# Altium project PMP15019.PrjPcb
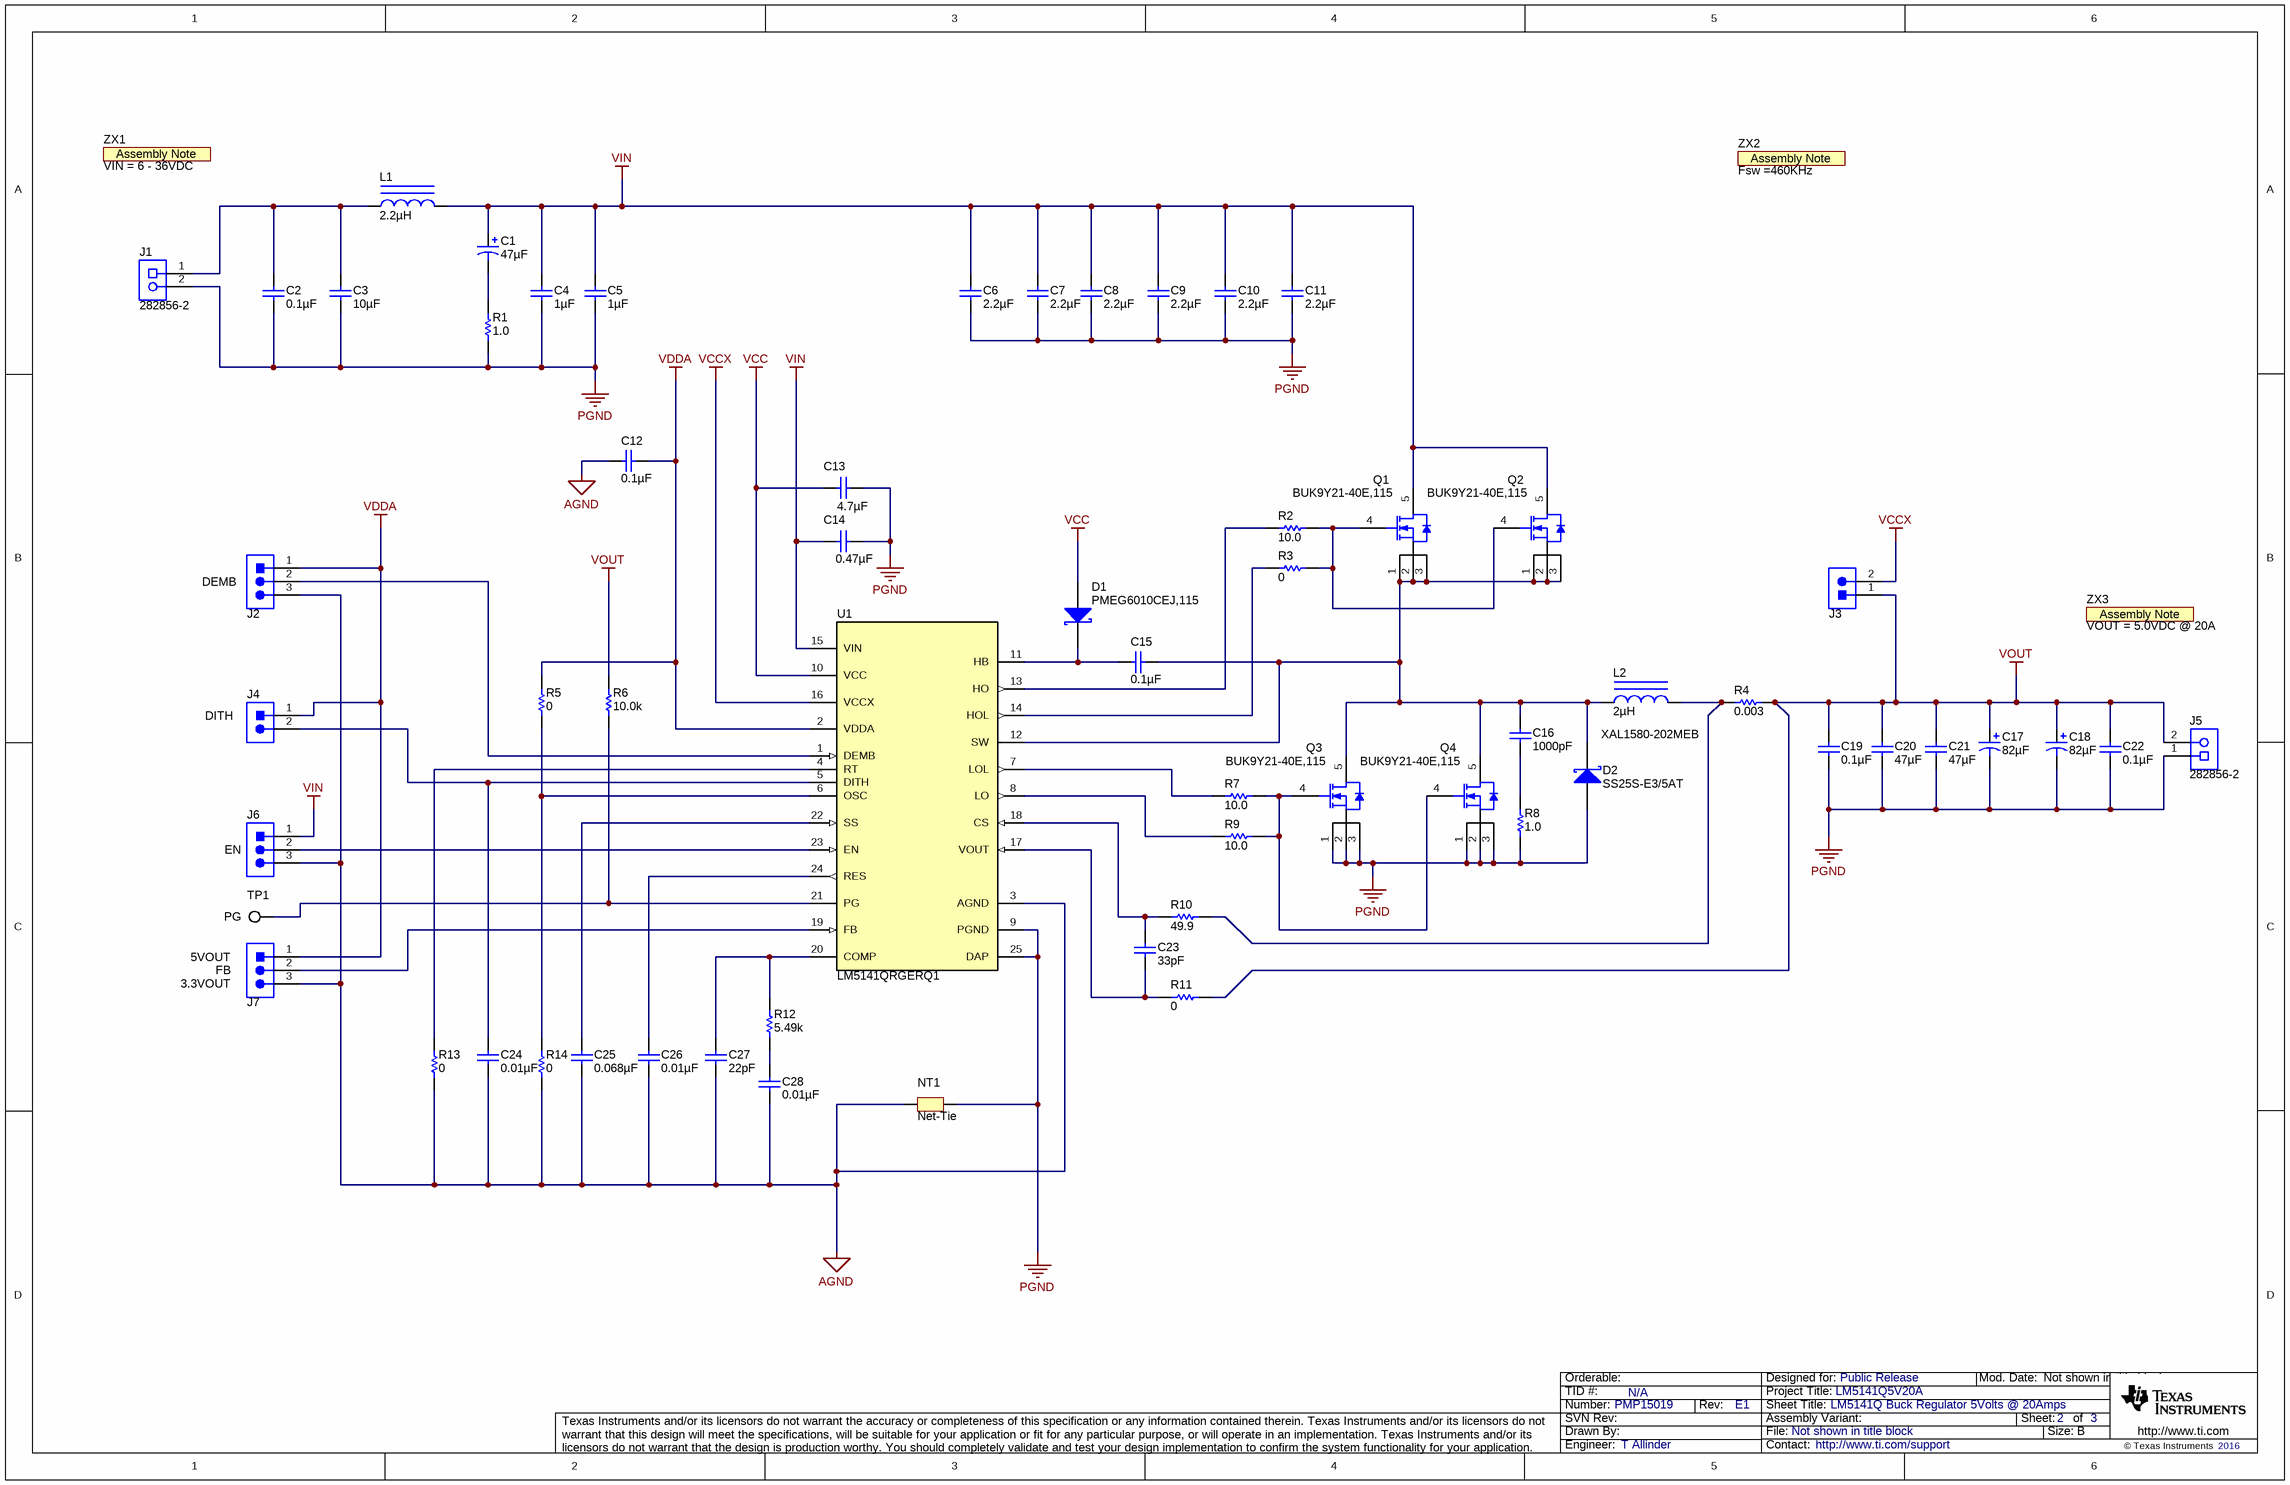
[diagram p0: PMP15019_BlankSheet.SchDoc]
TID: N/A; TechSupport: http://www.ti.com/support; SCH_Rev: E1; PRJ_Title: LM5141Q5V20A; PRJ_Number: PMP15019; PRJ_Engineer: T Allinder; PRJ_Customer: Public Release; PCB_Rev: E1; PCB_Layout: K Nielson; CopyrightYear: 2016
2 sheets, 87 parts. Net scope: global (net labels, ports and power ports of the same name join across sheets).
Board file: PMP15019_PCB.PcbDoc
Sheets:
  PMP15019_BlankSheet.SchDoc
  PMP15019_EVM_Hardware.SchDoc

## Sheet PMP15019_BlankSheet.SchDoc: LM5141Q Buck Regulator 5Volts @ 20Amps
size 431 x 279 mm; Date: Not shown in title block; ApprovedBy: Not shown in title block; CheckedBy: Not shown in title block; Author: Not shown in title block; CompanyName: Not shown in title block; Engineer: Not shown in title block; Organization: Not shown in title block; Address1: Not shown in title block; Address2: Not shown in title block; Address3: Not shown in title block; Address4: Not shown in title block; DocumentNumber: 1; Revision: Use project parameter SCH_Rev; SheetNumber: 2; SheetTotal: 3; PageSetup: Record=PageOptions¦CenterHorizontal=True¦CenterVertical=True¦PrintScale=1.00¦XCorrection=1.00¦YCorrection=1.00¦PrintKind=0¦BorderSize=5000000¦LeftOffset=0¦BottomOffset=0¦Orientation=2¦PaperLength=1000¦PaperWidth=1000¦Scale=100¦PaperSource=15¦PrintQuality=600¦MediaType=1¦DitherType=10¦PaperKind=Letter¦PrintScaleMode=1

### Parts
C1  ValueDisplayed: 47µF  [SM_RADIAL_G]  (hidden comment: EEE-FC1H470P)
C2  ValueDisplayed: 0.1µF  [0805_HV]  (hidden comment: C0805C104K1RACTU)
C3  ValueDisplayed: 10µF  [1210_280]  (hidden comment: C3225X7R1H106M250AC)
C4  ValueDisplayed: 1µF  [1206L]  (hidden comment: C3216X7R2A105M160AA)
C5  ValueDisplayed: 1µF  [1206L]  (hidden comment: C3216X7R2A105M160AA)
C6  ValueDisplayed: 2.2µF  [1206_190]  (hidden comment: CL31B225KCHSNNE)
C7  ValueDisplayed: 2.2µF  [1206_190]  (hidden comment: CL31B225KCHSNNE)
C8  ValueDisplayed: 2.2µF  [1206_190]  (hidden comment: CL31B225KCHSNNE)
C9  ValueDisplayed: 2.2µF  [1206_190]  (hidden comment: CL31B225KCHSNNE)
C10  ValueDisplayed: 2.2µF  [1206_190]  (hidden comment: CL31B225KCHSNNE)
C11  ValueDisplayed: 2.2µF  [1206_190]  (hidden comment: CL31B225KCHSNNE)
C12  ValueDisplayed: 0.1µF  [0603L]  (hidden comment: C0603C104K5RACTU)
C13  ValueDisplayed: 4.7µF  [0603L]  (hidden comment: GRM188R61C475KAAJ)
C14  ValueDisplayed: 0.47µF  [0805L]  (hidden comment: GRM21BR72A474KA73L)
C15  ValueDisplayed: 0.1µF  [0603L]  (hidden comment: C0603C104K5RACTU)
C16  ValueDisplayed: 1000pF  [0603L]  (hidden comment: GRM1885C2A102JA01D)
C17  ValueDisplayed: 82µF  [WCAP-PSLP_630x580]  (hidden comment: 875105344009)
C18  ValueDisplayed: 82µF  [WCAP-PSLP_630x580]  (hidden comment: 875105344009)
C19  ValueDisplayed: 0.1µF  [0603L]  (hidden comment: C0603C104K5RACTU)
C20  ValueDisplayed: 47µF  [1206]  (hidden comment: C3216X5R1C476M160AB)
C21  ValueDisplayed: 47µF  [1206]  (hidden comment: C3216X5R1C476M160AB)
C22  ValueDisplayed: 0.1µF  [0603L]  (hidden comment: C0603C104K5RACTU)
C23  ValueDisplayed: 33pF  [0603L]  (hidden comment: 06035A330JAT2A)
C24  ValueDisplayed: 0.01µF  [0603L]  (hidden comment: CGA3E2X7R2A103K080AA)
C25  ValueDisplayed: 0.068µF  [0603L]  (hidden comment: GRM188R71E683KA01D)
C26  ValueDisplayed: 0.01µF  [0603L]  (hidden comment: CGA3E2X7R2A103K080AA)
C27  ValueDisplayed: 22pF  [0603L]  (hidden comment: CGA3E2C0G1H220J080AA)
C28  ValueDisplayed: 0.01µF  [0603L]  (hidden comment: CGA3E2X7R2A103K080AA)
D1  PMEG6010CEJ,115  [SOD-323F]
D2  SS25S-E3/5AT  [SMA]
J1  282856-2  [TE_282856-2]
J2  TSW-103-07-G-S  [TSW-103-07-G-S]  (value not drawn)
J3  TSW-102-07-G-S  [TSW-102-07-G-S]  (value not drawn)
J4  TSW-102-07-G-S  [TSW-102-07-G-S]  (value not drawn)
J5  282856-2  [TE_282856-2]
J6  TSW-103-07-G-S  [TSW-103-07-G-S]  (value not drawn)
J7  TSW-103-07-G-S  [TSW-103-07-G-S]  (value not drawn)
L1  ValueDisplayed: 2.2µH  [WE-HCC_1090]  (hidden comment: 7443330220)
L2  XAL1580-202MEB  ValueDisplayed: 2µH  [XAL1580]
NT1  Net-Tie  [Net-Tie_10mil]  (net tie, no BOM)
Q1  BUK9Y21-40E,115  [LFPAK56]
Q2  BUK9Y21-40E,115  [LFPAK56]
Q3  BUK9Y21-40E,115  [LFPAK56]
Q4  BUK9Y21-40E,115  [LFPAK56]
R1  ValueDisplayed: 1.0  [1206]  (hidden comment: CRCW12061R00JNEA)
R2  ValueDisplayed: 10.0  [0603S]  (hidden comment: CRCW060310R0FKEAHP)
R3  ValueDisplayed: 0  [0603S]  (hidden comment: CRCW06030000Z0EA)
R4  0.003  [2512_WIDE]
R5  ValueDisplayed: 0  [0603L]  (hidden comment: CRCW06030000Z0EA)
R6  ValueDisplayed: 10.0k  [0603L]  (hidden comment: CRCW060310K0FKEA)
R7  ValueDisplayed: 10.0  [0603S]  (hidden comment: CRCW060310R0FKEAHP)
R8  ValueDisplayed: 1.0  [1206]  (hidden comment: CRM1206-JW-1R0ELF)
R9  ValueDisplayed: 10.0  [0603S]  (hidden comment: CRCW060310R0FKEAHP)
R10  ValueDisplayed: 49.9  [0603L]  (hidden comment: CRCW060349R9FKEA)
R11  ValueDisplayed: 0  [0603L]  (hidden comment: CRCW06030000Z0EA)
R12  ValueDisplayed: 5.49k  [0603L]  (hidden comment: CRCW06035K49FKEA)
R13  ValueDisplayed: 0  [0603L]  (hidden comment: CRCW06030000Z0EA)
R14  ValueDisplayed: 0  [0603L]  (hidden comment: CRCW06030000Z0EA)
TP1  5002  [Keystone5002]  (value not drawn)
U1  LM5141QRGERQ1  [RGE0024H]
ZX1  VIN = 6 - 36VDC  [AssemblyNote]  (no BOM)
ZX2  Fsw =460KHz  [AssemblyNote]  (no BOM)
ZX3  VOUT = 5.0VDC @ 20A  [AssemblyNote]  (no BOM)

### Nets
AGND: C12.1 C24.2 C25.2 C26.2 C27.2 C28.2 J2.3 J6.3 J7.3 NT1.1 R13.1 R14.2 U1.3(AGND)
PGND: C2.2 C3.2 C4.2 C5.2 C6.2 C7.2 C8.2 C9.2 C10.2 C11.2 C13.1 C14.1 C17.2(-) C18.2(-) C19.2 C20.2 C21.2 C22.2 D2.2(A) J1.2 J5.1 NT1.2 Q3.1(S) Q3.2(S) Q3.3(S) Q4.1(S) Q4.2(S) Q4.3(S) R1.1 R8.1 U1.9(PGND) U1.25(DAP)
VCC: C13.2 D1.2(A) U1.10(VCC)
VCCX: J3.2 U1.16(VCCX)
VDDA: C12.2 J2.1 J4.1 J7.1 R5.1 U1.2(VDDA)
VIN: C1.1(+) C4.1 C5.1 C6.1 C7.1 C8.1 C9.1 C10.1 C11.1 C14.2 J6.1 L1.2 Q1.5(D) Q2.5(D) U1.15(VIN)
VOUT: C17.1(+) C18.1(+) C19.1 C20.1 C21.1 C22.1 J3.1 J5.2 R4.2 R6.1 R11.2
NetC1_2: C1.2(-) R1.2
NetC2_1: C2.1 C3.1 J1.1 L1.1
NetC15_1: C15.1 D1.1(K) U1.11(HB)
NetC15_2: C15.2 C16.1 D2.1(K) L2.1 Q1.1(S) Q1.2(S) Q1.3(S) Q2.1(S) Q2.2(S) Q2.3(S) Q3.5(D) Q4.5(D) U1.12(SW)
NetC16_2: C16.2 R8.2
NetC23_1: C23.1 R11.1 U1.17(VOUT)
NetC23_2: C23.2 R10.1 U1.18(CS)
NetC24_1: C24.1 J4.2 U1.5(DITH)
NetC25_1: C25.1 U1.22(SS)
NetC26_1: C26.1 U1.24(RES)
NetC27_1: C27.1 R12.2 U1.20(COMP)
NetC28_1: C28.1 R12.1
NetJ2_2: J2.2 U1.1(DEMB)
NetJ6_2: J6.2 U1.23(EN)
NetJ7_2: J7.2 U1.19(FB)
NetL2_2: L2.2 R4.1 R10.2
NetQ1_4: Q1.4(G) Q2.4(G) R2.2 R3.1
NetQ3_4: Q3.4(G) Q4.4(G) R7.2 R9.1
NetR2_1: R2.1 U1.13(HO)
NetR3_2: R3.2 U1.14(HOL)
NetR5_2: R5.2 R14.1 U1.6(OSC)
NetR6_2: R6.2 TP1.1 U1.21(PG)
NetR7_1: R7.1 U1.7(LOL)
NetR9_2: R9.2 U1.8(LO)
NetR13_2: R13.2 U1.4(RT)

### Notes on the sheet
- (near J2) DEMB
- (near J4) DITH
- (near J6) EN
- 5VOUT
- FB
- (near TP1) PG
- 3.3VOUT

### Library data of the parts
C1 = EEE-FC1H470P: CAP, AL, 47 µF, 50 V, +/- 20%, 0.3 ohm, SMD; Manufacturer: Panasonic; Polarized: Y; CompType: Capacitor; Value: 47uF; U/M: EA; Cap_F: 0.000047; Tolerance_%: 20; Value1: 0.3 ohm; VDC_V: 50; Value2: 50V; ESR_ohm: 0.3; IRMS_A: 0.5; TaMin_C: -40; TaMax_C: 105; Cap_Case: G
C2 = C0805C104K1RACTU: CAP, CERM, 0.1 µF, 100 V, +/- 10%, X7R, 0805; Manufacturer: Kemet; Polarized: N; CompType: Capacitor; Value: 0.1uF; U/M: EA; Cap_F: 0.0000001; Tolerance_%: 10; ESR_ohm: 0.064; Value1: 0.064 ohm; VDC_V: 100; Value2: 100V; IRMS_A: 1.64; TaMin_C: -55; TaMax_C: 125; Cap_Case: 0805
C3 = C3225X7R1H106M250AC: CAP, CERM, 10 µF, 50 V, +/- 20%, X7R, 1210; Manufacturer: TDK; Polarized: N; CompType: Capacitor; Value: 10uF; U/M: EA; Cap_F: 0.00001; Tolerance_%: 20; Value1: Unknown; VDC_V: 50; Value2: 50V; TaMin_C: -55; TaMax_C: 125; Cap_Case: 1210
C4 C5 = C3216X7R2A105M160AA: CAP, CERM, 1 µF, 100 V, +/- 20%, X7R, 1206; Manufacturer: TDK; Polarized: N; CompType: Capacitor; Value: 1uF; U/M: EA; Cap_F: 0.000001; Tolerance_%: 20; Value1: Unknown; VDC_V: 100; Value2: 100V; TaMin_C: -55; TaMax_C: 125; Cap_Case: 1206
C6-C11 = CL31B225KCHSNNE: CAP, CERM, 2.2 µF, 100 V, +/- 10%, X7R, 1206_190; Manufacturer: Samsung Electro-Mechanics; Polarized: N; CompType: Capacitor; Value: 2.2uF; U/M: EA; Cap_F: 0.0000022; Tolerance_%: 10; Value1: Unknown; VDC_V: 100; Value2: 100V; TaMin_C: -55; TaMax_C: 125; Cap_Case: 1206
C12 C15 C19 C22 = C0603C104K5RACTU: CAP, CERM, 0.1 µF, 50 V, +/- 10%, X7R, 0603; Manufacturer: Kemet; Polarized: N; CompType: Capacitor; Value: 0.1uF; U/M: EA; Cap_F: 0.0000001; Tolerance_%: 10; Value1: Unknown; VDC_V: 50; Value2: 50V; TaMin_C: -55; TaMax_C: 125; Cap_Case: 0603
C13 = GRM188R61C475KAAJ: CAP, CERM, 4.7 µF, 16 V, +/- 10%, X5R, 0603; Manufacturer: MuRata; Polarized: N; CompType: Capacitor; Value: 4.7uF; U/M: EA; Cap_F: 0.0000047; Tolerance_%: 10; Value1: Unknown; VDC_V: 16; Value2: 16V; TaMin_C: -55; TaMax_C: 85; Cap_Case: 0603
C14 = GRM21BR72A474KA73L: CAP, CERM, 0.47 µF, 100 V, +/- 10%, X7R, 0805; Manufacturer: MuRata; Polarized: N; CompType: Capacitor; Value: 0.47uF; U/M: EA; Cap_F: 0.00000047; Tolerance_%: 10; Value1: Unknown; VDC_V: 100; Value2: 100V; TaMin_C: -55; TaMax_C: 125; Cap_Case: 0805
C16 = GRM1885C2A102JA01D: CAP, CERM, 1000 pF, 100 V, +/- 5%, C0G/NP0, 0603; Manufacturer: MuRata; Polarized: N; CompType: Capacitor; Value: 1000pF; U/M: EA; Cap_F: 0.000000001; Tolerance_%: 5; Value1: Unknown; VDC_V: 100; Value2: 100V; TaMin_C: -55; TaMax_C: 125; Cap_Case: 0603
C17 C18 = 875105344009: CAP, Aluminum Polymer, 82 µF, 16 V, +/- 20%, 0.03 ohm, D6.3xL5.8mm SMD; Manufacturer: Wurth Elektronik; Polarized: Y; CompType: Capacitor; Value: 82uF; U/M: EA; Cap_F: 0.000082; Tolerance_%: 20; VDC_V: 16; Value2: 16V; ESR_ohm: 0.03; IRMS_A: 2.2; TaMin_C: -55; TaMax_C: 105; Cap_Case: 6.3x5.8mm
C20 C21 = C3216X5R1C476M160AB: CAP, CERM, 47 µF, 16 V, +/- 15%, X5R, 1206; Manufacturer: TDK; Polarized: N; CompType: Capacitor; Value: 47uF; U/M: EA; Cap_F: 0.000047; Tolerance_%: 15; Value1: Unknown; VDC_V: 16; Value2: 16V; TaMin_C: -55; TaMax_C: 85
C23 = 06035A330JAT2A: CAP, CERM, 33 pF, 50 V, +/- 5%, C0G/NP0, 0603; Manufacturer: AVX; Polarized: N; CompType: Capacitor; Value: 33pF; U/M: EA; Cap_F: 0.000000000033; Tolerance_%: 5; ESR_ohm: 0.209; Value1: 0.209 ohm; VDC_V: 50; Value2: 50V; TaMin_C: -55; TaMax_C: 125; Cap_Case: 0603
C24 C26 C28 = CGA3E2X7R2A103K080AA: CAP, CERM, 0.01 µF, 100 V, +/- 10%, X7R, AEC-Q200 Grade 1, 0603; Manufacturer: TDK; Polarized: N; CompType: Capacitor; Value: 0.01uF; U/M: EA; Cap_F: 0.00000001; Tolerance_%: 10; ESR_ohm: 0.235428; Value1: 0.235428 ohm; VDC_V: 100; Value2: 100V; IRMS_A: 0.396995; TaMin_C: -55; TaMax_C: 125; Cap_Case: 0603; SizeArea_mm2: 1.28; SizeAreaWB_mm2: 4.68; SizeX_mm: 1.6; SizeY_mm: 0.8; SizeZ_mm: 1; AEC Category: Q200; AEC Qualified: Y
C25 = GRM188R71E683KA01D: CAP, CERM, 0.068 µF, 25 V, +/- 10%, X7R, 0603; Manufacturer: MuRata; Polarized: N; CompType: Capacitor; Value: 0.068uF; U/M: EA; Cap_F: 0.000000068; Tolerance_%: 10; Value1: Unknown; VDC_V: 25; Value2: 25V; TaMin_C: -55; TaMax_C: 125; Cap_Case: 0603
C27 = CGA3E2C0G1H220J080AA: CAP, CERM, 22 pF, 50 V, +/- 5%, C0G/NP0, AEC-Q200 Grade 1, 0603; Manufacturer: TDK; Polarized: N; CompType: Capacitor; Value: 22pF; U/M: EA; Cap_F: 0.000000000022; Tolerance_%: 5; Value1: Unknown; VDC_V: 50; Value2: 50V; TaMin_C: -55; TaMax_C: 125; Cap_Case: 0603; SizeArea_mm2: 1.28; SizeAreaWB_mm2: 4.68; SizeX_mm: 1.6; SizeY_mm: 0.8; SizeZ_mm: 1; AEC Category: Q200; AEC Qualified: Y
D1 = PMEG6010CEJ,115: Diode, Schottky, 60 V, 1 A, SOD-323F; Manufacturer: NXP Semiconductor; U/M: EA; Vf_V: 0.66; Value: 60V; Value1: 1A; Value2: 0.66V; Io_A: 1; Vr_V: 60; TJmax_C: 150
D2 = SS25S-E3/5AT: Diode, Schottky, 50 V, 2 A, AEC-Q101, SMA; Manufacturer: Vishay-Semiconductor; U/M: EA; Vf_V: 0.75; Value: 50V; Value1: 2A; Value2: 0.75V; Io_A: 2; Vr_V: 50; TJmax_C: 150; SizeAreaWB_mm2: 37.3428; SizeArea_mm2: 16.3228; SizeX_mm: 5.59; SizeY_mm: 2.92; SizeZ_mm: 2.87; AEC Category: Q101; AEC Qualified: Y
J1 J5 = 282856-2: Therminal Block, 5 mm, 2-pole, Tin, TH; Manufacturer: TE Connectivity; SymbolCreator: a0412235; CompType: Terminal Block
J2 J6 J7 = TSW-103-07-G-S: Header, 100mil, 3x1, Gold, TH; Manufacturer: Samtec; SymbolCreator: a0799628; U/M: EA
J3 J4 = TSW-102-07-G-S: Header, 100mil, 2x1, Gold, TH; Manufacturer: Samtec; SymbolCreator: a0412235; U/M: EA
L1 = 7443330220: Inductor, Shielded Drum Core, Ferrite, 2.2 µH, 16.5 A, 0.0037 ohm, SMD; Manufacturer: Wurth Elektronik; Value: 2.2uH; Ind_H: 2.2E-6; Imax_A: 16.5; Irms: 16.5A @ 50C rise; Isat: 22A @ 30% inductance drop; DCR_ohm: 0.0037; Value2: 16.5A; AEC Category: Q200
L2 = XAL1580-202MEB: Inductor, Shielded, Composite, 2 µH, 39.9 A, 0.001909 ohm, SMD; Manufacturer: Coilcraft; Value: 2uH; Ind_H: 2.0E-6; Imax_A: 39.9; Irms: 39.9A @ 40C rise; Isat: 51A @ 0.7% inductance drop; Value2: 39.9A; AEC Category: Q200
NT1 = Net-Tie: Single point connection between nets.; SymbolCreator: codlsc
Q1-Q4 = BUK9Y21-40E,115: MOSFET, N-CH, 40 V, 33 A, AEC-Q101, SOT669; Manufacturer: NXP Semiconductor; Alternate Manufacturer: None; SymbolCreator: a0412235; U/M: EA; ChType: N; Value: 40V; VdsMax_V: 40; Value1: ? ohm; Value2: 7 nC; QgTyp_nC: 7; Vgs_V: 10; IdsMax_A: 33; SizeAreaWB_mm2: 55.2; SizeArea_mm2: 29.4; SizeX_mm: 4.9; SizeY_mm: 6; SizeZ_mm: 1.1; AEC Category: Q101; AEC Qualified: Y
R1 = CRCW12061R00JNEA: RES, 1.0, 5%, 0.25 W, 1206; Manufacturer: Vishay-Dale; CompType: Resistor; Value: 1.0; Res_ohm: 1; Value_Code: 1R00; Tolerance_%: 5; Power_W: 0.25; Value2: 0.25W; VDC_V: 200; TempCo: 200 ppm/C; EIA_Code: E24; U/M: EA
R2 R7 R9 = CRCW060310R0FKEAHP: RES, 10.0, 1%, 0.25 W, 0603; Manufacturer: Vishay-Dale; CompType: Resistor; Value: 10.0; Res_ohm: 10; Value_Code: 10R0; Tolerance_%: 1; Power_W: 0.25; Value2: 0.25W; VDC_V: 75; TempCo: 100 ppm/C; EIA_Code: E96; U/M: EA
R3 R5 R11 R14 = CRCW06030000Z0EA: RES, 0, 5%, 0.1 W, 0603; Manufacturer: Vishay-Dale; CompType: Resistor; Value: 0; Value_Code: 0000; Tolerance_%: 5; Power_W: 0.1; Value2: 0.1W; VDC_V: 75; TempCo: 200 ppm/C; EIA_Code: E24; U/M: EA
R4 = KRL6432E-M-R003-F-T1: RES SMD 0.003 OHM 3W 2512 WIDE; Manufacturer: Susumu; SymbolCreator: a0413446; CompType: Used in some BOM reports.  Useful for finding later.; U/M: EA; Tolerance_%: ±1%; TempCo: ±50ppm/°C
R6 = CRCW060310K0FKEA: RES, 10.0 k, 1%, 0.1 W, 0603; Manufacturer: Vishay-Dale; CompType: Resistor; Value: 10.0k; Res_ohm: 10000; Value_Code: 10k0; Tolerance_%: 1; Power_W: 0.1; Value2: 0.1W; VDC_V: 75; TempCo: 100 ppm/C; EIA_Code: E96; U/M: EA
R8 = CRM1206-JW-1R0ELF: RES, 1.0, 5%, 0.5 W, 1206; Manufacturer: Bourns; CompType: Resistor; Value: 1.0; Res_ohm: 1; Value_Code: 1R00; Tolerance_%: 5; Power_W: 0.5; Value2: 0.5W; TempCo: 150 ppm/C; EIA_Code: E24; U/M: EA
R10 = CRCW060349R9FKEA: RES, 49.9, 1%, 0.1 W, 0603; Manufacturer: Vishay-Dale; CompType: Resistor; Value: 49.9; Value_Code: 49R9; Tolerance_%: 1; Power_W: 0.1; Value2: 0.1W; VDC_V: 75; TempCo: 100 ppm/C; EIA_Code: E96; U/M: EA
R12 = CRCW06035K49FKEA: RES, 5.49 k, 1%, 0.1 W, 0603; Manufacturer: Vishay-Dale; CompType: Resistor; Value: 5.49k; Res_ohm: 5490; Value_Code: 5k49; Tolerance_%: 1; Power_W: 0.1; Value2: 0.1W; VDC_V: 75; TempCo: 100 ppm/C; EIA_Code: E96; U/M: EA; SizeArea_mm2: 1.28; SizeX_mm: 1.6; SizeY_mm: 0.8; AEC Category: Q200
R13 = CRCW06030000Z0EA: RES, 0, 5%, 0.1 W, 0603; Manufacturer: Vishay-Dale; CompType: Resistor; Value: 0; Value_Code: 0000; Tolerance_%: 5; Power_W: 0.1; Value2: 0.1W; VDC_V: 75; TempCo: 200 ppm/C; EIA_Code: E24; U/M: EA; SizeArea_mm2: 1.28; SizeX_mm: 1.6; SizeY_mm: 0.8; SizeZ_mm: 1; AEC Category: Q200
TP1 = 5002: Test Point, Miniature, White, TH; Manufacturer: Keystone; CompType: Test Point Loop; U/M: EA
U1 = LM5141QRGERQ1: Wide Input Range Buck Controller, RGE0024H; Manufacturer: Texas Instruments; SymbolCreator: Altium; SizeArea_mm2: 16; SizeAreaWB_mm2: 25; SizeX_mm: 4; SizeZ_mm: 1; CompType: IC; U/M: EA
ZX1-ZX3 = AssemblyNote: This Assembly Note will show in the PcbDoc and associated outputs; SymbolCreator: codlsc

## Sheet PMP15019_EVM_Hardware.SchDoc: LM5141Q Buck Regulator 5Volt @ 20 Amps HW
size 431 x 279 mm; Date: Not shown in title block; ApprovedBy: Not shown in title block; CheckedBy: Not shown in title block; Author: Not shown in title block; CompanyName: Not shown in title block; Engineer: Not shown in title block; Organization: Not shown in title block; Address1: Not shown in title block; Address2: Not shown in title block; Address3: Not shown in title block; Address4: Not shown in title block; DocumentNumber: 1; Revision: Use project parameter SCH_Rev; SheetNumber: 3; SheetTotal: 3; PageSetup: Record=PageOptions¦CenterHorizontal=True¦CenterVertical=True¦PrintScale=1.00¦XCorrection=1.00¦YCorrection=1.00¦PrintKind=0¦BorderSize=5000000¦LeftOffset=0¦BottomOffset=0¦Orientation=2¦PaperLength=1000¦PaperWidth=1000¦Scale=100¦PaperSource=15¦PrintQuality=600¦MediaType=1¦DitherType=10¦PaperKind=Letter¦PrintScaleMode=1
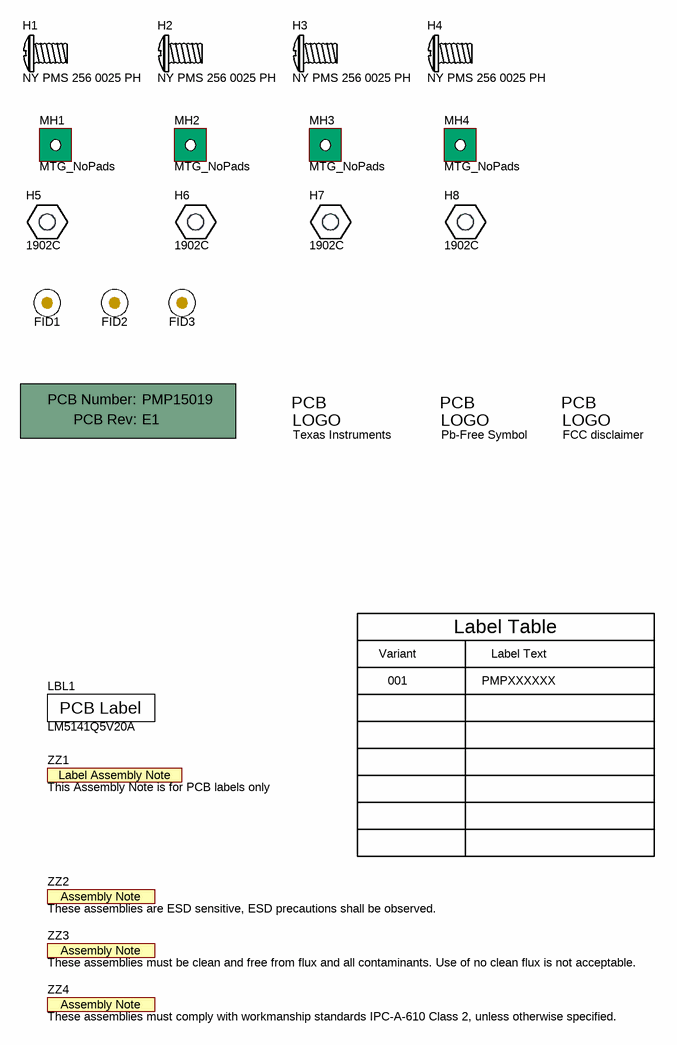
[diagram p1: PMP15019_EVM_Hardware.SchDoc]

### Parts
!PCB1  Printed Circuit Board  (value not drawn)  (mechanical)
FID1  Fiducial  [Fiducial10-20]  (value not drawn)
FID2  Fiducial  [Fiducial10-20]  (value not drawn)
FID3  Fiducial  [Fiducial10-20]  (value not drawn)
H1  NY PMS 256 0025 PH  (mechanical)
H2  NY PMS 256 0025 PH  (mechanical)
H3  NY PMS 256 0025 PH  (mechanical)
H4  NY PMS 256 0025 PH  (mechanical)
H5  1902C  [Keystone_1902C]
H6  1902C  [Keystone_1902C]
H7  1902C  [Keystone_1902C]
H8  1902C  [Keystone_1902C]
LBL1  LM5141Q5V20A  [Label_650x200]
Logo1  Texas Instruments  [TI_Stacked_Overlay_Small]  (no BOM)
Logo2  Pb-Free Symbol  [Pb-Free_Overlay_Small]  (no BOM)
Logo3  FCC disclaimer  [FCC_disclaimer]  (no BOM)
MH1  MTG_NoPads  [MTG_159mil]  (no BOM)
MH2  MTG_NoPads  [MTG_159mil]  (no BOM)
MH3  MTG_NoPads  [MTG_159mil]  (no BOM)
MH4  MTG_NoPads  [MTG_159mil]  (no BOM)
ZZ1  This Assembly Note is for PCB labels only  [AssemblyNoteLabel]  (no BOM)
ZZ2  These assemblies are ESD sensitive, ESD precautions shall be observed.  [AssemblyNote]  (no BOM)
ZZ3  These assemblies must be clean and free from flux and all contaminants. Use of no clean flux is not acceptable.  [AssemblyNote]  (no BOM)
ZZ4  These assemblies must comply with workmanship standards IPC-A-610 Class 2, unless otherwise specified.  [AssemblyNote]  (no BOM)

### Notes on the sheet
- Variant
- Label Table
- Label Text
- 001
- PMPXXXXXX

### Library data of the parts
!PCB1 = PCB: Manufacturer: Any; PartNumber: PMP15019; SymbolCreator: a0412235
FID1-FID3 = Fiducial: Fiducial mark.  There is nothing to buy or mount.; SymbolCreator: codlsc
H1-H4 = NY PMS 256 0025 PH: Nylon Screw, Panhead, Phillips, 2-56; Manufacturer: B&F Fastener Supply; SymbolCreator: a0412235
H5-H8 = 1902C: Standoff, Hex, 0.5"L #4-40 Nylon; Manufacturer: Keystone; CompType: Hardware
LBL1 = THT-14-423-10: Thermal Transfer Printable Labels, 0.650" W x 0.200" H - 10,000 per roll; Manufacturer: Brady; SymbolCreator: a0412235; CompType: Label
Logo1 = TI_Logo: Texas Instrument Corporate Signature; SymbolCreator: codlsc
Logo2 = Pb-Free: SymbolCreator: a0412235
Logo3 = FCC_disclaimer: SymbolCreator: codlsc
MH1-MH4 = Mounting Hole (non-standard) No Pad: PCB Mounting Hole, No Pad; Manufacturer: Any; SymbolCreator: a0412235
ZZ1 = AssemblyNoteLabel: SymbolCreator: a0412235
ZZ2-ZZ4 = AssemblyNote: SymbolCreator: codlsc

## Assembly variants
001: not fitted FID1 FID2 FID3 R5 R6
